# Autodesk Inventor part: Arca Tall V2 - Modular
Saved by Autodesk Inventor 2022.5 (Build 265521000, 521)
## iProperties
Created: 2025-01
Part Number: Arca Tall V2 - Modular
Material: Generic
Document SubType Name: Modeling
Designer: AdminForWorker
Density: 1 g/cm^3
Appearance: Default
Title: Arca Tall V2 - Modular
Author: AdminForWorker
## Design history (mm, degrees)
feature "Arca Tall V2 - Modular"
body "Solid1"
